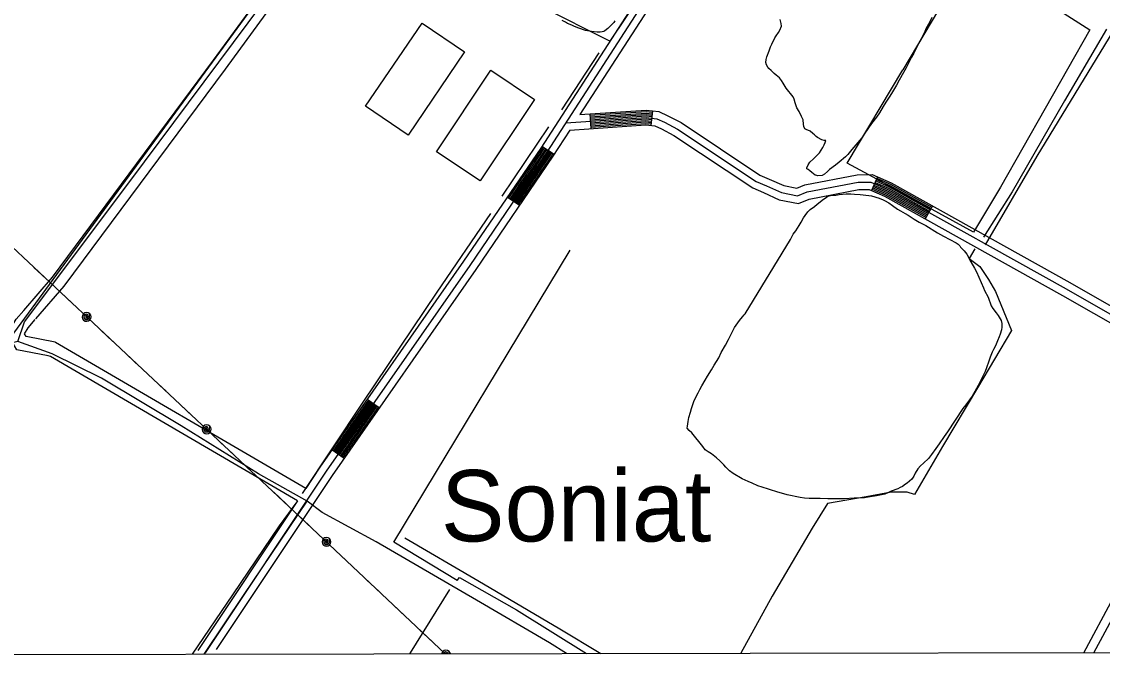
# Model space of a CAD drawing. Extents: x 3324125 to 3362000, y 600753 to 626151.
# Drawn here: x 3333814 to 3336010, y 606134 to 607430 of the extents above; entities that cross this region are included whole.
import ezdxf

# ---------------------------------------------------------------- set-up
doc = ezdxf.new("R2010")
doc.units = 0
for name, color, linetype in [('V-BLDG-OTLN', 7, 'Continuous'), ('V-DTCH-CNTR', 7, 'Continuous'), ('V-GRID-FRAM', 7, 'Continuous'), ('V-ROAD-CNTR', 7, 'Continuous'), ('V-SITE-VEGE', 7, 'Continuous'), ('V-TOPO-GNAM-IDEN', 7, 'Continuous'), ('V-TOPO-SHOR', 7, 'Continuous'), ('V-UTIL-LINE', 7, 'Continuous')]:
    doc.layers.add(name, color=color, linetype=linetype)

msp = doc.modelspace()

# ---------------------------------------------------------------- linework, layer by layer
at = {"layer": 'V-BLDG-OTLN'}
for points in [[(3334512.7, 607258), (3334627.6, 607427), (3334714, 607368.3), (3334599.1, 607199.2)], [(3334656.8, 607165.5), (3334767.4, 607330.9), (3334855.8, 607271.8), (3334745.2, 607106.4)]]:
    msp.add_lwpolyline(points, close=True, dxfattribs=at)
at = {"layer": 'V-DTCH-CNTR'}
msp.add_line((3335744, 607566.6), (3335604.7, 607332), dxfattribs=at)
for points in [[(3333805.7, 606780.2), (3333819.2, 606820.3), (3334033.6, 607104.8), (3334304, 607467.5), (3334317.4, 607485.5), (3334331, 607504), (3334456.9, 607675.5), (3334493.8, 607725.7), (3334600.6, 607868.3), (3334627.4, 607904), (3334699.6, 608000.1), (3334868.9, 608230.9), (3334892.8, 608263.5), (3335082.6, 608518.5), (3335284.4, 608789.5), (3335426, 608739.8), (3335698.8, 608651.2), (3335817.3, 608615.7), (3335842.7, 608604)], [(3335744, 607566.6), (3335984.3, 607412.9), (3335803.3, 607093.7), (3335747.8, 607001.9), (3335544.3, 607113.7), (3335491.1, 607142.4), (3335604.7, 607332)], [(3335772.8, 606976.2), (3335877.8, 607156.4), (3336041.7, 607425.5)], [(3334393.8, 606455.7), (3334295, 606511.6), (3334137.9, 606608.7), (3333976.3, 606705.7), (3333875.6, 606754.8), (3333805.7, 606780.2), (3333764.5, 606770), (3333667.2, 606827.4), (3333601.8, 606870.4), (3333569.6, 606891.6), (3333560.9, 606897.5), (3333392.5, 607012.6), (3333211.1, 607142), (3333078.8, 607233.2)], [(3334184.7, 606144.9), (3334265.8, 606266), (3334393.8, 606455.7)], [(3334921.1, 606146.2), (3334886.6, 606167.9), (3334737.9, 606254.8), (3334534.3, 606373), (3334424.1, 606432.5), (3334393.8, 606455.7)], [(3334592.5, 606381.6), (3334740.7, 606295), (3334907.7, 606196.4), (3334990.6, 606146.3)], [(3335992.5, 606148), (3336043.5, 606241.9)]]:
    msp.add_lwpolyline(points, dxfattribs=at)
at = {"layer": 'V-GRID-FRAM'}
msp.add_lwpolyline([(3328210, 624318.2), (3328233.8, 606134.5), (3359834, 606189.7), (3359794.3, 624373.3), (3328210, 624318.2)], dxfattribs=at)
at = {"layer": 'V-ROAD-CNTR'}
for p, q in [((3334968.2, 607242.5), (3334970.2, 607212.5)), ((3335095.6, 607248.8), (3335092.1, 607219)), ((3334895.8, 607160.1), (3334870.6, 607176.4)), ((3335552.9, 607114.5), (3335541, 607086.9)), ((3334825.3, 607056.4), (3334800.5, 607073.3)), ((3335664.8, 607055.6), (3335650.1, 607029.4)), ((3334540.5, 606645.3), (3334515.9, 606662.4)), ((3334468.9, 606542.8), (3334444.3, 606560))]:
    msp.add_line(p, q, dxfattribs=at)
for points in [[(3335952.6, 608768.7), (3335847.7, 608616.5), (3335547.4, 608163.8), (3335294.8, 607785.1), (3335081.8, 607475.2), (3334881, 607164.8), (3334724.2, 606934.6), (3334432.3, 606516.5), (3334186.6, 606148)], [(3335965, 608760.2), (3335860.1, 608608.1), (3335559.9, 608155.5), (3335307.2, 607776.7), (3335094.3, 607466.9), (3334948.2, 607241.1)], [(3335820.8, 608603.1), (3335534.9, 608172.1), (3335282.4, 607793.5), (3335069.3, 607483.5), (3334868.5, 607173.1), (3334711.9, 606943.2), (3334419.9, 606525), (3334390.9, 606481.5)], [(3333817.8, 606843.1), (3333876.3, 606911.1), (3334203.7, 607351.3), (3334593.5, 607884.4), (3334849.6, 608225.8)], [(3333842.7, 606826), (3333899.8, 606892.3), (3334227.9, 607333.5), (3334617.6, 607866.5), (3334872.7, 608206.6)], [(3334948.2, 607241.1), (3335083, 607250.2), (3335108.8, 607247.2), (3335127, 607238.8), (3335154.1, 607224.7), (3335313.9, 607118.3), (3335333.1, 607110.1), (3335362.4, 607096.8), (3335389.1, 607091.4), (3335405.5, 607098.3), (3335511.9, 607118.8), (3335542.4, 607119), (3335580.7, 607102.5), (3335943.6, 606899.9), (3336315.9, 606687.7)], [(3334968.4, 607239.5), (3335083, 607247.2), (3335095.3, 607245.8)], [(3334968.6, 607236.5), (3335082.9, 607244.2), (3335094.9, 607242.8)], [(3334968.8, 607233.5), (3335082.8, 607241.2), (3335094.6, 607239.8)], [(3334969, 607230.5), (3335082.8, 607238.2), (3335094.2, 607236.8)], [(3334919.3, 607224.1), (3335082.7, 607235.2), (3335104.6, 607232.6), (3335120.4, 607225.3), (3335146.5, 607211.7), (3335306.7, 607105.1), (3335327.1, 607096.4), (3335357.8, 607082.5), (3335390.7, 607075.8), (3335409.9, 607083.9), (3335513.4, 607103.8), (3335539.4, 607104), (3335574.1, 607089), (3335936.2, 606886.8), (3336304.8, 606676.8), (3336344, 606654.7), (3336458.5, 606522.8), (3336578.5, 606347.9), (3336725.8, 606152.4)], [(3334927.9, 607209.7), (3335082.3, 607220.1), (3335100.5, 607218), (3335113.8, 607211.8), (3335138.9, 607198.8), (3335299.6, 607091.9), (3335321, 607082.6), (3335353.2, 607068.1), (3335392.3, 607060.2), (3335414.2, 607069.4), (3335514.8, 607088.8), (3335536.3, 607088.9), (3335567.4, 607075.5), (3335928.9, 606873.8), (3336297.4, 606663.7), (3336302.4, 606660.9)], [(3334969.2, 607227.5), (3335082.7, 607235.2), (3335093.9, 607233.9)], [(3334969.4, 607224.5), (3335082.6, 607232.2), (3335093.5, 607230.9)], [(3334969.6, 607221.5), (3335082.5, 607229.1), (3335093.2, 607227.9)], [(3334969.8, 607218.5), (3335082.5, 607226.1), (3335092.8, 607224.9)], [(3334970, 607215.5), (3335082.4, 607223.1), (3335092.5, 607221.9)], [(3334927.9, 607209.7), (3334893.4, 607156.5), (3334736.6, 606926.1), (3334444.7, 606508.1), (3334208.9, 606154.4)], [(3334873.1, 607174.7), (3334871, 607171.4), (3334803, 607071.6)], [(3334875.6, 607173.1), (3334873.5, 607169.8), (3334805.5, 607069.9)], [(3334878.1, 607171.5), (3334876, 607168.1), (3334807.9, 607068.2)], [(3334880.7, 607169.9), (3334878.5, 607166.5), (3334810.4, 607066.5)], [(3334883.2, 607168.2), (3334881, 607164.8), (3334812.9, 607064.9)], [(3334885.7, 607166.6), (3334883.5, 607163.1), (3334815.4, 607063.2)], [(3334888.2, 607165), (3334885.9, 607161.5), (3334817.9, 607061.5)], [(3334890.7, 607163.3), (3334888.4, 607159.8), (3334820.3, 607059.8)], [(3334893.2, 607161.7), (3334890.9, 607158.2), (3334822.8, 607058.1)], [(3335550.5, 607108.9), (3335578, 607097.1), (3335661.8, 607050.3)], [(3335551.7, 607111.7), (3335579.4, 607099.8), (3335663.3, 607052.9)], [(3335542.2, 607089.7), (3335568.7, 607078.2), (3335651.6, 607032)], [(3335543.4, 607092.4), (3335570.1, 607080.9), (3335653.1, 607034.6)], [(3335544.6, 607095.2), (3335571.4, 607083.6), (3335654.5, 607037.2)], [(3335545.8, 607097.9), (3335572.7, 607086.3), (3335656, 607039.8)], [(3335547, 607100.7), (3335574.1, 607089), (3335657.5, 607042.5)], [(3335548.2, 607103.4), (3335575.4, 607091.7), (3335658.9, 607045.1)], [(3335549.3, 607106.2), (3335576.7, 607094.4), (3335660.4, 607047.7)], [(3333867.5, 606750.8), (3333804.1, 606763.3), (3333784.8, 606795.6), (3333802.5, 606825.3), (3333817.8, 606843.1)], [(3333881.6, 606778.6), (3333823, 606790.2), (3333819.8, 606795.6), (3333827, 606807.8), (3333841.4, 606824.5)], [(3334390.9, 606481.5), (3333882.8, 606778.4), (3333881.6, 606778.6)], [(3334374.2, 606456.5), (3333872, 606749.9), (3333867.5, 606750.8)], [(3334518.3, 606660.7), (3334446.8, 606558.2)], [(3334520.8, 606659), (3334449.2, 606556.5)], [(3334523.2, 606657.3), (3334451.7, 606554.8)], [(3334525.7, 606655.6), (3334454.1, 606553.1)], [(3334528.2, 606653.9), (3334456.6, 606551.4)], [(3334530.6, 606652.1), (3334459.1, 606549.7)], [(3334533.1, 606650.4), (3334461.5, 606547.9)], [(3334535.5, 606648.7), (3334464, 606546.2)], [(3334538, 606647), (3334466.4, 606544.5)], [(3334374.2, 606456.5), (3334171.5, 606152.3)]]:
    msp.add_lwpolyline(points, dxfattribs=at)
at = {"layer": 'V-SITE-VEGE'}
for points in [[(3335663.7, 607437.9), (3335659.4, 607429.5), (3335651.4, 607415), (3335648.2, 607407.5), (3335642, 607395.1), (3335637.3, 607386.6), (3335631, 607374.2), (3335626.6, 607366), (3335621.9, 607357.8), (3335611.1, 607335.8), (3335605.8, 607326.2), (3335597.1, 607310.9), (3335591.9, 607300.7), (3335583.6, 607287), (3335577.9, 607278.3), (3335569.8, 607265.9), (3335564.7, 607257.2), (3335556.8, 607244.3), (3335550.8, 607235.7), (3335540.8, 607222.6), (3335526, 607201.5), (3335520.9, 607194), (3335513.1, 607184), (3335501.1, 607169.8), (3335492.6, 607160.1), (3335488.1, 607154.9), (3335475.2, 607144.3), (3335467.9, 607138.6), (3335455.4, 607129.3), (3335451.4, 607125.5), (3335445.3, 607119.9), (3335440.4, 607117.3), (3335432, 607116.6), (3335429.8, 607117.3), (3335426.2, 607118), (3335419.8, 607123.1), (3335415.8, 607126.7), (3335411.8, 607129.2), (3335409.2, 607130.5), (3335409.4, 607132.9), (3335412.3, 607139.2), (3335415.6, 607144.2), (3335422.8, 607151.4), (3335435, 607163.3), (3335438.6, 607168.7), (3335441.7, 607174.4), (3335444.6, 607179.3), (3335446.7, 607184.6), (3335447.8, 607188.2), (3335444.7, 607188.6), (3335440.2, 607190), (3335431.1, 607194.2), (3335428.5, 607196.2), (3335424.7, 607199.8), (3335421.8, 607202.9), (3335416.5, 607207.2), (3335408.2, 607210.8), (3335405.6, 607212.3), (3335403.1, 607217), (3335402.9, 607221.6), (3335401.8, 607230.5), (3335398.8, 607237.2)], [(3335019.4, 607431.4), (3335016.9, 607428.3), (3335012.4, 607423.4), (3335004.9, 607415.9), (3334998.9, 607411), (3334996.9, 607409.7), (3334993.3, 607408.8), (3334989.7, 607408.4), (3334983.3, 607408.4), (3334971.5, 607409.5), (3334959.9, 607412.1), (3334945.7, 607416.8), (3334937.5, 607419.9), (3334931.7, 607422.3), (3334923.3, 607426.2), (3334918.7, 607428.6), (3334912, 607431.9)], [(3335398.8, 607237.2), (3335393.5, 607247.5), (3335389.3, 607254.4), (3335385.5, 607264.8), (3335383.7, 607272.6), (3335381.7, 607277.3), (3335367.6, 607294.5), (3335361.1, 607304.5), (3335357.6, 607310.2), (3335353.8, 607315.6), (3335346.8, 607321.2), (3335343.2, 607324.3), (3335337, 607330.8), (3335332.4, 607334.5), (3335330.3, 607337), (3335327.5, 607342.3), (3335326.2, 607346.6), (3335326.6, 607353.2), (3335328, 607358.1), (3335332.6, 607370.8), (3335335.8, 607378.6), (3335338.2, 607384.1), (3335344.1, 607396.6), (3335346.8, 607400.8), (3335351.7, 607407.6), (3335354.8, 607412.7), (3335357.7, 607420.7), (3335357.3, 607426.1), (3335354.9, 607434.3)], [(3335284.3, 606836.3), (3335376.3, 606987.4), (3335381.9, 606997.9), (3335386.8, 607004.7), (3335393.9, 607015.4), (3335398.2, 607022.7), (3335402.9, 607031.4), (3335406, 607036), (3335411.4, 607043.3), (3335416.5, 607048), (3335425.2, 607054.6), (3335430.1, 607058.8), (3335436.8, 607063.9), (3335440.6, 607067.3), (3335449.4, 607073.2), (3335452.4, 607075), (3335457.5, 607076.6), (3335468.1, 607077.6), (3335475.3, 607078.7), (3335489.3, 607080.2), (3335498.6, 607080), (3335506.6, 607079.7), (3335517.7, 607079), (3335535.5, 607077), (3335541.1, 607075.7), (3335556.2, 607071), (3335564.8, 607068), (3335567.1, 607066.7), (3335575.9, 607061.5), (3335583.4, 607056.6), (3335593.5, 607049.1), (3335599.7, 607045.3), (3335609, 607040.4), (3335615, 607036.8), (3335627.2, 607028.7), (3335637.6, 607022.7), (3335651.1, 607015.8), (3335674.7, 607001), (3335687.3, 606994.1), (3335712.9, 606980.5), (3335717.1, 606978), (3335720.4, 606974.5), (3335722, 606972), (3335728.8, 606964), (3335734.6, 606957.3), (3335742.8, 606941.7), (3335750.3, 606929.3), (3335754.3, 606921.3), (3335758.7, 606910.6), (3335768.2, 606888.8), (3335770.6, 606883.9), (3335777.7, 606870.1), (3335783.9, 606852.3), (3335787.4, 606846.9), (3335794, 606838.6), (3335798.5, 606832.9)], [(3335798.5, 606832.9), (3335804.2, 606822.8), (3335805.6, 606816.4), (3335806, 606809.1), (3335805.1, 606803.5), (3335802.6, 606794.8), (3335800.6, 606789.5), (3335797, 606781.7), (3335792.6, 606771.5), (3335788.8, 606763.7), (3335786.3, 606758.2), (3335782, 606748), (3335779.1, 606740), (3335774.6, 606726.9), (3335771.5, 606718.9), (3335766.6, 606708.2), (3335757.9, 606690.9), (3335750.9, 606678.3), (3335745.2, 606669), (3335732.2, 606651.7), (3335726.6, 606644.1), (3335711, 606620.1), (3335695.1, 606596.6), (3335688.2, 606587.1), (3335678.2, 606572.4), (3335671.3, 606562.9), (3335662.6, 606550.4), (3335656.5, 606542.5), (3335646.7, 606533), (3335640.5, 606527.4), (3335634.9, 606521.8), (3335629.3, 606512.5), (3335626.9, 606506.8), (3335623.1, 606500.8), (3335613.3, 606492.4), (3335610.2, 606490.1), (3335603.9, 606485.9), (3335599.2, 606483.3), (3335594.1, 606480.8), (3335581, 606475.8), (3335575.6, 606473.5), (3335567.9, 606470.3), (3335561.4, 606468.9), (3335551.2, 606466.9), (3335533.8, 606463.9), (3335526.3, 606462.8), (3335513.2, 606462), (3335505.4, 606461.9), (3335486.2, 606460.9), (3335474.2, 606460.5), (3335452.2, 606460.6), (3335436.7, 606461.2), (3335414, 606461.3), (3335404.7, 606462.2), (3335396, 606463.6), (3335369.6, 606468.6), (3335348.4, 606475.1), (3335335.4, 606478.6), (3335331.4, 606480.2), (3335318.5, 606484.3), (3335309.8, 606486.9), (3335298, 606492.1), (3335290, 606496.1), (3335278.3, 606501.2), (3335259.6, 606511.7), (3335252.3, 606517.1), (3335244.6, 606524.7), (3335241, 606529.6), (3335232.3, 606537.8), (3335225.9, 606543.9), (3335215.5, 606552.1), (3335209.1, 606556.3), (3335203.1, 606560.4), (3335197.8, 606566.6), (3335189.8, 606577.1), (3335183.8, 606584.2), (3335175.8, 606594.5), (3335170.5, 606599.4), (3335166.3, 606604.1), (3335166.7, 606608.3), (3335167.9, 606617.8), (3335169.4, 606625.6), (3335173.1, 606636.9), (3335174.8, 606644.1), (3335180.2, 606660), (3335188.3, 606675.8), (3335192.1, 606682.9), (3335195.7, 606690.2), (3335202.8, 606701.5), (3335207.5, 606709.5), (3335215.8, 606722.6), (3335221.3, 606732), (3335230.3, 606747), (3335235.2, 606757.9), (3335243.9, 606773), (3335250.1, 606784.3), (3335262.7, 606808.5), (3335272.3, 606822.7), (3335278.5, 606830), (3335281.8, 606834.3), (3335284.3, 606836.3)]]:
    msp.add_lwpolyline(points, dxfattribs=at)
at = {"layer": 'V-TOPO-SHOR'}
for p, q in [((3333798.1, 606797), (3334289, 607466.8)), ((3334911.7, 607250.9), (3334987.1, 607366.4)), ((3334790.2, 607075.4), (3334884.9, 607216.1))]:
    msp.add_line(p, q, dxfattribs=at)
for points in [[(3334866.8, 607461.7), (3335010, 607390.1), (3335332.1, 607870.8)], [(3336018.2, 607414.6), (3335933.1, 607268.8), (3335826.4, 607084.3), (3335768.1, 606992)], [(3334384.4, 606471.3), (3334508, 606657.2), (3334658.1, 606880.6), (3334767.2, 607040.1)], [(3334699, 606295), (3334570.2, 606372.5), (3334928.2, 606965.7)], [(3335750.6, 606968.1), (3335739.3, 606948.6), (3335760.8, 606932.3), (3335778.5, 606906.1), (3335793.1, 606881.6), (3335825.4, 606802.7), (3335756.5, 606685.7), (3335685.3, 606566.6), (3335628.5, 606469.4)], [(3335972.6, 606148), (3336032.5, 606260), (3336172.5, 606513.2), (3336262.3, 606673.2)], [(3335628.5, 606469.4), (3335613.2, 606474.4), (3335580.5, 606474.3), (3335529.9, 606464.8), (3335451.7, 606451.1), (3335420.3, 606400.7), (3335338.8, 606263.1), (3335275.3, 606146.8)], [(3334160.9, 606144.8), (3334242.7, 606265.4), (3334337.6, 606406), (3334373.4, 606454.8)], [(3334699, 606295), (3334703.7, 606300.7), (3334819.2, 606234.9), (3334961.5, 606146.2)], [(3334602.3, 606145.6), (3334603.7, 606147.8), (3334683.8, 606276.2)]]:
    msp.add_lwpolyline(points, dxfattribs=at)
at = {"layer": 'V-UTIL-LINE'}
for points in [[(3332702.9, 608150.5), (3333255, 607481.7), (3333749.9, 607013.7), (3334356.7, 606445.3), (3334674.4, 606145.7)], [(3333838.6, 606930.6), (3333863.4, 606907.3)], [(3333892.6, 606880), (3333917.4, 606856.7)], [(3333945.9, 606830.1), (3333946.3, 606832.9), (3333944.2, 606831.9), (3333943.9, 606829.1), (3333946.2, 606827.4), (3333948.7, 606829.8), (3333948.6, 606834.5), (3333944.6, 606835.8), (3333940.5, 606833.3), (3333940.4, 606828.7), (3333942.9, 606825), (3333947.7, 606824.7), (3333951.7, 606828.5), (3333952, 606836.6), (3333949.1, 606838.5), (3333945.6, 606839.1), (3333942.2, 606838.3), (3333939.3, 606836.2), (3333937.5, 606833.2), (3333936.9, 606829.8), (3333937.7, 606826.4), (3333939.7, 606823.5), (3333942.7, 606821.6), (3333946.2, 606821.1), (3333949.6, 606821.9), (3333952.5, 606823.9), (3333954.3, 606826.9), (3333954.9, 606830.4), (3333954.1, 606833.8), (3333952, 606836.6)], [(3333974.4, 606803.4), (3333999.2, 606780.2)], [(3334028.4, 606752.8), (3334053.2, 606729.6)], [(3334082.4, 606702.2), (3334107.2, 606679)], [(3334136.4, 606651.7), (3334161.2, 606628.4)], [(3334189.7, 606601.8), (3334190.1, 606604.6), (3334188, 606603.6), (3334187.7, 606600.8), (3334190, 606599.1), (3334192.5, 606601.4), (3334192.4, 606606.1), (3334188.4, 606607.5), (3334184.2, 606605), (3334184.2, 606600.4), (3334186.7, 606596.7), (3334191.5, 606596.4), (3334195.5, 606600.2), (3334195.8, 606608.3), (3334192.8, 606610.2), (3334189.4, 606610.7), (3334186, 606610), (3334183.1, 606607.9), (3334181.3, 606604.9), (3334180.7, 606601.5), (3334181.5, 606598), (3334183.5, 606595.2), (3334186.5, 606593.3), (3334190, 606592.8), (3334193.4, 606593.6), (3334196.2, 606595.6), (3334198.1, 606598.6), (3334198.7, 606602), (3334197.9, 606605.5), (3334195.8, 606608.3)], [(3334218.1, 606575.1), (3334243, 606551.9)], [(3334272.2, 606524.5), (3334297, 606501.3)], [(3334326.2, 606473.9), (3334351, 606450.7)], [(3334380.1, 606423.3), (3334404.8, 606399.9)], [(3334433.2, 606373.2), (3334433.6, 606376), (3334431.6, 606375), (3334431.2, 606372.3), (3334433.6, 606370.5), (3334436, 606372.9), (3334436, 606377.6), (3334431.9, 606378.9), (3334427.8, 606376.4), (3334427.7, 606371.8), (3334430.2, 606368.1), (3334435, 606367.8), (3334439, 606371.6), (3334439.4, 606379.7), (3334436.4, 606381.6), (3334432.9, 606382.2), (3334429.5, 606381.4), (3334426.7, 606379.4), (3334424.8, 606376.4), (3334424.2, 606372.9), (3334425, 606369.5), (3334427, 606366.6), (3334430, 606364.8), (3334433.5, 606364.2), (3334436.9, 606365), (3334439.8, 606367), (3334441.6, 606370), (3334442.2, 606373.4), (3334441.4, 606376.9), (3334439.4, 606379.7)], [(3334461.6, 606346.4), (3334486.3, 606323.1)], [(3334515.4, 606295.7), (3334540.2, 606272.3)], [(3334569.3, 606244.9), (3334594, 606221.6)], [(3334623.1, 606194.1), (3334647.8, 606170.8)], [(3334682.2, 606145.8), (3334682.4, 606150.6), (3334679.4, 606152.5), (3334676, 606153), (3334672.5, 606152.3), (3334669.7, 606150.2), (3334667.8, 606147.2), (3334667.5, 606145.7)], [(3334679, 606145.7), (3334679, 606148.4), (3334674.9, 606149.8), (3334670.8, 606147.3), (3334670.8, 606145.7)], [(3334676.5, 606145.7), (3334676.6, 606146.9), (3334674.6, 606145.9), (3334674.5, 606145.7)], [(3334684.9, 606145.8), (3334684.4, 606147.7), (3334682.4, 606150.6)]]:
    msp.add_lwpolyline(points, dxfattribs=at)

# ---------------------------------------------------------------- texts
at = {"layer": 'V-TOPO-GNAM-IDEN'}
msp.add_text('Soniat', height=145, rotation=359.9873, dxfattribs=at).set_placement((3334665.7, 606374.1))

doc.saveas('drawing.dxf')
